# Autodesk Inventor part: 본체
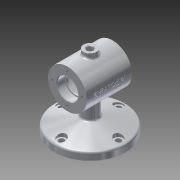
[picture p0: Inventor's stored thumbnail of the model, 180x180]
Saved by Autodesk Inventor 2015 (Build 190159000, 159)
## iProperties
Created: 2018-12
Part Number: 본체
Material: 알루미늄 6061
Document SubType Name: Modeling
Designer: now
Density: 2.7 g/cm^3
Appearance: 알루미늄 - 평지
Mass: 685.366 g
Surface Area: 556.634 cm^2
Volume: 253.839 cm^3
Author: now
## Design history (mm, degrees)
sketch "스케치1"
  geometry: C1 r 55 at (0, 0); 1 further point
  constraints: 1 centre point, 1 coincident
  dimensions: "d0" = 110 diameter of C1
extrude "돌출1" new body sketch "스케치1" distance "d1" = 11; taper "d2" = 0 deg
sketch "스케치2"
  geometry: C1 r 55 at (0, 0) reference; C2 r 12 at (0, 0)
  constraints: 1 centre point, 1 coincident
  dimensions: "d3" = 24 diameter of C2
extrude "돌출2" join sketch "스케치2" distance "d4" = 75; taper "d5" = 0 deg
sketch "스케치3"
  geometry: L1 (-55, 0)-(-55, 11) reference; L2 (-55, 11)-(-12, 11) reference; L3 (-12, 11)-(-12, 86) reference; L4 (-12, 86)-(12, 86) reference; L5 (12, 86)-(12, 11) reference; L6 (12, 11)-(55, 11) reference; L7 (55, 11)-(55, 0) reference; L8 (55, 0)-(-55, 0) reference; L9 (55, 11)-(12, 22.522); L10 (12, 22.522)-(0, 22.522); L11 (0, 22.522)-(0, 11); L12 (55, 11)-(-55, 11) reference; L13 (12, 11)-(55, 11); L14 (12, 11)-(0, 11); 1 further point
  constraints: 10 end point, 3 horizontal, 1 midpoint, 1 point on line
  dimensions: "d6" = 75 deg angle of L7 L9
revolve "회전1" sketch "스케치3" stored, may be unused: angle "d7" = 90 deg
fillet "모깎기1" dims "d8" = 3
sketch "스케치5"
  geometry: L1 (-52.776, 11.596)-(-12, 22.522) reference; L2 (-12, 22.522)-(-12, 86) reference; L3 (-12, 86)-(12, 86) reference; L4 (12, 86)-(12, 22.522) reference; L5 (12, 22.522)-(52.776, 11.596) reference; L6 (55, 8.698)-(55, 0) reference; L7 (55, 0)-(-55, 0) reference; L8 (-55, 0)-(-55, 8.698) reference; C1 r 30 at (0, 75); A1 r 3 centre (-52, 8.698) between (-52.776, 11.596) and (-55, 8.698) reference; A2 r 3 centre (52, 8.698) between (55, 8.698) and (52.776, 11.596) reference; 3 further points
  constraints: 1 centre point, 1 coincident, 1 midpoint, 1 vertical alignment
  dimensions: "d9" = 75 distance from line of L7 point (0, 75); "d10" = 60 diameter of C1
extrude "돌출3" join sketch "스케치5" stored distance "d11" = 70; taper "d12" = 0 deg
sketch "스케치6"
  geometry: C1 r 30 at (0, 0) reference; 1 further point
hole "구멍1" sketch "스케치6" at (0, 0) diameter "d13" = 28; stored, may be unused: countersink angle "d17" = 90 deg, drill point angle "d19" = 0 deg; dims "d14" = 6, "d15" = 32, "d16" = 12, "d18" = 15
sketch "스케치7"
  geometry: C1 r 14 at (0, 0) reference; 1 further point
hole "구멍2" sketch "스케치7" at (0, 0) diameter "d20" = 50; stored, may be unused: countersink angle "d24" = 90 deg, drill point angle "d26" = 0 deg; dims "d21" = 6, "d22" = 32, "d23" = 12, "d25" = 40
fillet "모깎기2" dims "d27" = 0.3
sketch "스케치8"
  geometry: C1 r 16 at (0, 0) reference; 2 further points
  constraints: 1 vertical alignment
  dimensions: "d28" = 23 distance of C1.centre point (0, 23)
hole "구멍3" sketch "스케치8" at (0, 23) diameter "d29" = 3.242; stored, may be unused: countersink angle "d33" = 90 deg, drill point angle "d35" = 118 deg; dims "d30" = 8, "d31" = 32, "d32" = 12, "d34" = 10
fillet "모깎기3" dims "d39" = 3
node "작업 평면1"
sketch "스케치9"
  geometry: L1 (-30, -35)-(30, -35) reference; C1 r 10 at (0, 0); 1 further point
  constraints: 1 centre point, 1 coincident
  dimensions: "d41" = 35 distance from line of C1.centre L1; "d42" = 20 diameter of C1
extrude "돌출4" join sketch "스케치9" stored distance "d43" = 70; taper "d44" = 0 deg
sketch "스케치10"
  geometry: C1 r 10 at (0, 0) reference
hole "구멍4" sketch "스케치10" at (0, 0) diameter "d45" = 10; stored, may be unused: countersink angle "d49" = 90 deg, drill point angle "d51" = 0 deg; dims "d46" = 8, "d47" = 32, "d48" = 12, "d50" = 10
chamfer "모따기1" distance "d52" = 1; stored, may be unused: second distance "d53" = 2, angle "d54" = 45 deg
sketch "스케치11" dims "d55" = 88
  geometry: C1 r 55 at (0, 0) reference; C2 r 4.5 at (-44, 0); 1 further point
  constraints: 2 horizontal alignment, 1 centre point, 1 coincident, 2 other
  dimensions: "d56" = 9 diameter of C2
extrude "돌출5" cut sketch "스케치11" distance "d57" = 10; taper "d58" = 0 deg
sketch "스케치12"
  geometry: C1 r 4.5 at (0, 0) reference; C2 r 7 at (0, 0); 1 further point
  constraints: 1 centre point, 1 coincident
  dimensions: "d59" = 14 diameter of C2
extrude "돌출6" cut sketch "스케치12" stored distance "d60" = 10; taper "d61" = 0 deg
fillet "모깎기4" dims "d65" = 3
fillet "모깎기5" dims "d66" = 3
node "작업 평면2"
sketch "스케치13" dims "d1" = 11, "d2" = 0, "d8" = 3
  geometry: L1 (-35, 105)-(-35, 45) reference; 2 further points
  constraints: 1 other
  dimensions: "d68" = 35 distance from line of L1 point (0, 75); "d69" = 30 vertical distance of L1.start point (0, 75)
feature "엠보싱1" sketch "스케치13" dims "d8" = 3, "d70" = 0.5, "d71" = 0
chamfer "모따기2" distance "d72" = 1; stored, may be unused: second distance "d73" = 2, angle "d74" = 45 deg
node "솔리드1"
mirror "대칭1"
pattern_circular "원형 패턴1" dims angle "d37" = 360 deg
mirror "대칭2"
pattern_circular "원형 패턴2" dims angle "d63" = 360 deg
node "절단 모서리 투영1"
node "절단 모서리 투영3"
other parameters: "d40" = 112, "d67" = 70.75
